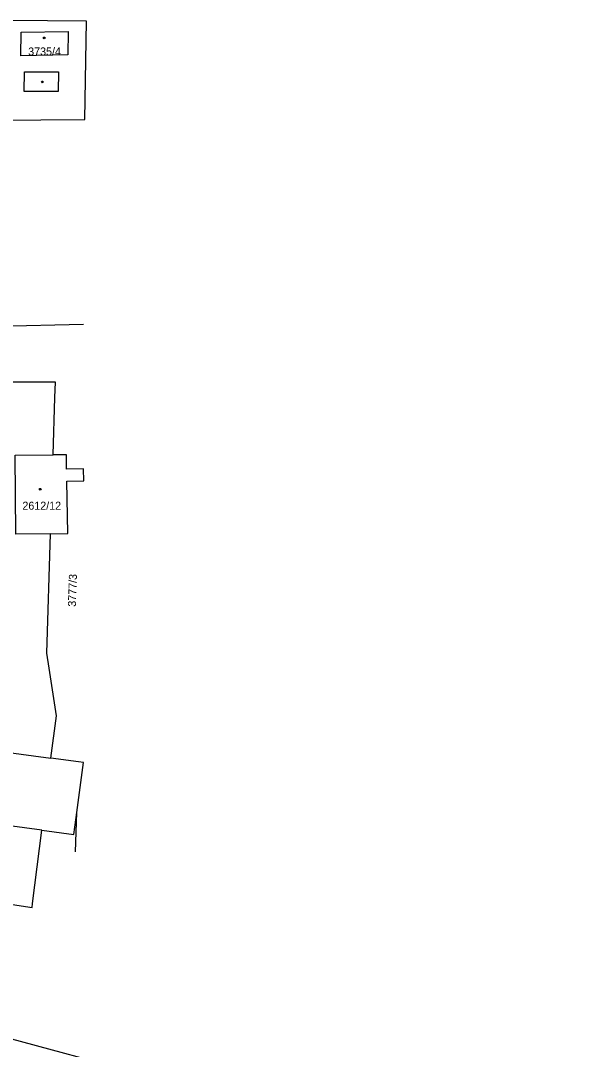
# Model space of a CAD drawing. Extents: x -527335 to -526256, y -1079142 to -1077836.
# Drawn here: x -526375.8 to -526255.8, y -1078442 to -1078223.5 of the extents above; entities that cross this region are included whole.
import ezdxf

# ---------------------------------------------------------------- set-up
doc = ezdxf.new("R2010")
doc.units = 0
for name, color, linetype in [('Hranice parcel', 7, 'Continuous'), ('Parcelní čísla', 7, 'Continuous'), ('Vnitřní kresba', 7, 'Continuous'), ('Značky budov', 7, 'Continuous')]:
    doc.layers.add(name, color=color, linetype=linetype)

msp = doc.modelspace()

# ---------------------------------------------------------------- linework, layer by layer
at = {"layer": 'Hranice parcel'}
for p, q in [((-526361.75, -1078223.62), (-526378.34, -1078223.51)), ((-526363.48, -1078380.94), (-526369.31, -1078380.15)), ((-526364.12, -1078400.1), (-526363.84, -1078391.74))]:
    msp.add_line(p, q, dxfattribs=at)
for points in [[(-526380.88, -1078244.69), (-526362.1, -1078244.53), (-526361.75, -1078223.62)], [(-526368.35, -1078300.3), (-526392.03, -1078300.3), (-526433.75, -1078302.47), (-526450.54, -1078303.34), (-526493.09, -1078313.52), (-526500.68, -1078315.9), (-526538.39, -1078327.72)], [(-526368.84, -1078315.76), (-526368.46, -1078303.54), (-526368.35, -1078300.3)], [(-526369.38, -1078332.51), (-526376.77, -1078332.6), (-526376.93, -1078315.85), (-526368.84, -1078315.76)], [(-526369.38, -1078332.51), (-526365.74, -1078332.47), (-526365.95, -1078321.31), (-526362.36, -1078321.26), (-526362.41, -1078318.7), (-526365.99, -1078318.77), (-526366.04, -1078315.73), (-526368.84, -1078315.76)], [(-526369.31, -1078380.15), (-526368.16, -1078371.16), (-526369.73, -1078361.06), (-526370.19, -1078357.9), (-526369.38, -1078332.51)], [(-526371.27, -1078395.48), (-526431.8, -1078387.34), (-526429.78, -1078372), (-526369.31, -1078380.15)], [(-526363.84, -1078391.74), (-526362.41, -1078381.08), (-526363.48, -1078380.94)], [(-526371.27, -1078395.48), (-526364.47, -1078396.4), (-526363.84, -1078391.74)], [(-526373.3, -1078411.92), (-526373.26, -1078411.04), (-526371.27, -1078395.48)], [(-526564.52, -1078422.23), (-526553.55, -1078417.76), (-526496.54, -1078407.33), (-526464.62, -1078404.48), (-526434.2, -1078404.33), (-526403.84, -1078407.24), (-526373.3, -1078411.92)], [(-526255.84, -1078485.88), (-526269.44, -1078477.46), (-526275.29, -1078479.08), (-526290.24, -1078467.75), (-526298.87, -1078468), (-526349.1, -1078447.58), (-526381.09, -1078438.93), (-526412.01, -1078434.75), (-526470.91, -1078435.12), (-526515.41, -1078439.88), (-526541.88, -1078447.21), (-526576.22, -1078459.13), (-526589.61, -1078459.9), (-526628.8, -1078481.46), (-526632.26, -1078483.8)]]:
    msp.add_lwpolyline(points, dxfattribs=at)
at = {"layer": 'Vnitřní kresba'}
for p, q in [((-526375.68, -1078231.02), (-526375.67, -1078225.95)), ((-526375.67, -1078225.95), (-526365.69, -1078225.81)), ((-526365.69, -1078225.81), (-526365.72, -1078230.81)), ((-526365.72, -1078230.81), (-526375.68, -1078231.02)), ((-526374.99, -1078238.59), (-526374.91, -1078234.4)), ((-526374.91, -1078234.4), (-526367.72, -1078234.43)), ((-526367.72, -1078234.43), (-526367.81, -1078238.6)), ((-526367.81, -1078238.6), (-526374.99, -1078238.59)), ((-526362.42, -1078288.09), (-526395.78, -1078288.82))]:
    msp.add_line(p, q, dxfattribs=at)
at = {"layer": 'Značky budov'}
for centre in [(-526370.75, -1078227.18), (-526371.16, -1078236.53), (-526371.59, -1078323.04)]:
    msp.add_circle(centre, 0.175, dxfattribs=at)

# ---------------------------------------------------------------- texts
at = {"layer": 'Parcelní čísla'}
for s, p in [('3735/4', (-526374.15, -1078230.92)), ('2612/12', (-526375.38, -1078327.4))]:
    msp.add_text(s, height=1.7, dxfattribs=at).set_placement(p)
msp.add_text('3777/3', height=1.7, rotation=88, dxfattribs=at).set_placement((-526364.03, -1078348.03))

doc.saveas('drawing.dxf')
